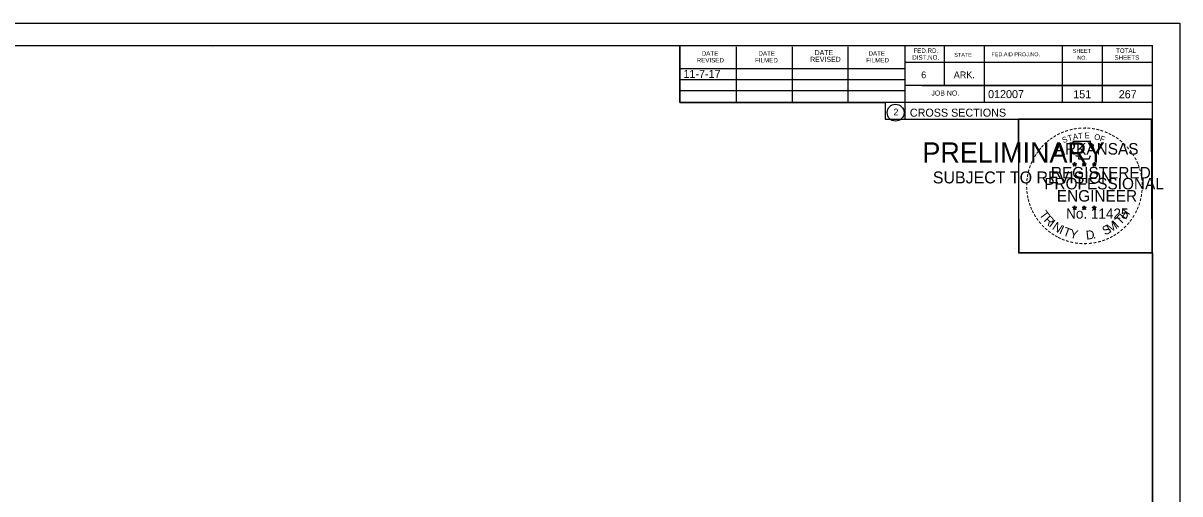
# Model space of a CAD drawing. Extents: x 1374311 to 1383814, y 384102 to 406278.
# Drawn here: x 1381590.3 to 1381791.6, y 384882.8 to 384964.6 of the extents above; entities that cross this region are included whole.
import ezdxf

# ---------------------------------------------------------------- set-up
doc = ezdxf.new("R2010")
doc.units = 0
for name, color, linetype in [('R_Border', 7, 'Continuous'), ('R_Border PE', 7, 'Continuous'), ('R_Border Prem', 7, 'Continuous'), ('R_Fin Surface', 7, 'Continuous'), ('R_No Plot', 7, 'Continuous'), ('R_Water', 7, 'Continuous')]:
    doc.layers.add(name, color=color, linetype=linetype)

msp = doc.modelspace()

# ---------------------------------------------------------------- linework, layer by layer
at = {"layer": 'R_Border'}
for p, q in [((1381470.66, 384960.72), (1381786.84, 384960.72)), ((1381623.18, 384960.46), (1381623.18, 384960.46)), ((1381623.18, 384960.46), (1381623.18, 384960.46)), ((1381704.58, 384950.84), (1381704.58, 384960.72)), ((1381714.44, 384950.84), (1381714.44, 384960.52)), ((1381724.2, 384950.84), (1381724.2, 384960.52)), ((1381733.88, 384950.84), (1381733.88, 384960.52)), ((1381743.74, 384960.72), (1381743.74, 384947.92)), ((1381750.58, 384960.72), (1381750.58, 384953.78)), ((1381757.52, 384960.72), (1381757.52, 384950.84)), ((1381771.1, 384960.72), (1381771.1, 384950.84)), ((1381778.04, 384960.72), (1381778.04, 384950.84)), ((1381786.84, 384755.26), (1381786.84, 384960.72)), ((1381786.84, 384957.78), (1381743.74, 384957.78)), ((1381786.84, 384957.8), (1381786.84, 384957.8)), ((1381704.58, 384956.7), (1381743.74, 384956.7)), ((1381704.58, 384954.84), (1381743.74, 384954.84)), ((1381704.58, 384950.84), (1381704.58, 384952.9)), ((1381704.58, 384952.9), (1381743.74, 384952.9)), ((1381786.84, 384953.78), (1381743.74, 384953.78)), ((1381746.7, 384953.78), (1381786.84, 384953.78)), ((1381786.84, 384950.84), (1381704.58, 384950.84)), ((1381743.74, 384947.92), (1381786.84, 384947.92))]:
    msp.add_line(p, q, dxfattribs=at)
msp.add_circle((1381742.12, 384949.05), 1.47, dxfattribs=at)
at = {"layer": 'R_Border PE'}
for p, q in [((1381772.92, 384940.17), (1381773.27, 384940.06)), ((1381772.92, 384940.17), (1381773.18, 384940.13)), ((1381772.92, 384940.17), (1381773.16, 384940.05)), ((1381773.06, 384939.77), (1381773.27, 384940.06)), ((1381773.06, 384939.77), (1381773.18, 384940.01)), ((1381773.06, 384939.77), (1381773.27, 384939.98)), ((1381773.27, 384940.43), (1381773.23, 384940.18)), ((1381773.27, 384940.06), (1381773.27, 384940.43)), ((1381773.27, 384940.43), (1381773.32, 384940.18)), ((1381773.62, 384940.17), (1381773.27, 384940.06)), ((1381773.48, 384939.77), (1381773.27, 384940.06)), ((1381773.48, 384939.77), (1381773.27, 384939.98)), ((1381773.62, 384940.17), (1381773.33, 384940.12)), ((1381773.48, 384939.77), (1381773.35, 384940.06)), ((1381773.62, 384940.17), (1381773.41, 384940.07)), ((1381774.59, 384940.17), (1381774.94, 384940.06)), ((1381774.59, 384940.17), (1381774.85, 384940.13)), ((1381774.59, 384940.17), (1381774.83, 384940.05)), ((1381774.73, 384939.77), (1381774.94, 384940.06)), ((1381774.73, 384939.77), (1381774.85, 384940.01)), ((1381774.73, 384939.77), (1381774.94, 384939.98)), ((1381774.94, 384940.43), (1381774.9, 384940.18)), ((1381774.94, 384940.06), (1381774.94, 384940.43)), ((1381774.94, 384940.43), (1381774.99, 384940.18)), ((1381775.29, 384940.17), (1381774.94, 384940.06)), ((1381775.15, 384939.77), (1381774.94, 384940.06)), ((1381775.15, 384939.77), (1381774.94, 384939.98)), ((1381775.29, 384940.17), (1381775, 384940.12)), ((1381775.15, 384939.77), (1381775.02, 384940.06)), ((1381775.29, 384940.17), (1381775.08, 384940.07)), ((1381776.36, 384940.16), (1381776.71, 384940.05)), ((1381776.36, 384940.16), (1381776.61, 384940.12)), ((1381776.36, 384940.16), (1381776.59, 384940.04)), ((1381776.49, 384939.75), (1381776.71, 384940.05)), ((1381776.49, 384939.75), (1381776.62, 384940)), ((1381776.49, 384939.75), (1381776.7, 384939.97)), ((1381776.71, 384940.42), (1381776.66, 384940.16)), ((1381776.92, 384939.75), (1381776.7, 384939.97)), ((1381776.71, 384940.05), (1381776.71, 384940.42)), ((1381776.71, 384940.42), (1381776.75, 384940.17)), ((1381777.05, 384940.16), (1381776.71, 384940.05)), ((1381776.92, 384939.75), (1381776.71, 384940.05)), ((1381777.05, 384940.16), (1381776.77, 384940.11)), ((1381776.92, 384939.75), (1381776.78, 384940.04)), ((1381777.05, 384940.16), (1381776.85, 384940.06)), ((1381773.27, 384932.85), (1381773.23, 384932.6)), ((1381773.27, 384932.49), (1381773.27, 384932.85)), ((1381773.27, 384932.85), (1381773.32, 384932.6)), ((1381774.94, 384932.85), (1381774.9, 384932.6)), ((1381774.94, 384932.49), (1381774.94, 384932.85)), ((1381774.94, 384932.85), (1381774.99, 384932.6)), ((1381776.7, 384932.84), (1381776.66, 384932.59)), ((1381776.7, 384932.48), (1381776.7, 384932.84)), ((1381776.7, 384932.84), (1381776.75, 384932.59)), ((1381772.92, 384932.6), (1381773.27, 384932.49)), ((1381772.92, 384932.6), (1381773.17, 384932.56)), ((1381772.92, 384932.6), (1381773.16, 384932.48)), ((1381773.05, 384932.19), (1381773.27, 384932.49)), ((1381773.05, 384932.19), (1381773.18, 384932.44)), ((1381773.05, 384932.19), (1381773.27, 384932.41)), ((1381773.61, 384932.6), (1381773.27, 384932.49)), ((1381773.48, 384932.19), (1381773.27, 384932.49)), ((1381773.48, 384932.19), (1381773.27, 384932.41)), ((1381773.61, 384932.6), (1381773.33, 384932.55)), ((1381773.48, 384932.19), (1381773.34, 384932.48)), ((1381773.61, 384932.6), (1381773.41, 384932.5)), ((1381774.59, 384932.6), (1381774.94, 384932.49)), ((1381774.59, 384932.6), (1381774.84, 384932.56)), ((1381774.59, 384932.6), (1381774.82, 384932.48)), ((1381774.72, 384932.19), (1381774.94, 384932.49)), ((1381774.72, 384932.19), (1381774.85, 384932.44)), ((1381774.72, 384932.19), (1381774.93, 384932.41)), ((1381775.15, 384932.19), (1381774.93, 384932.41)), ((1381775.28, 384932.6), (1381774.94, 384932.49)), ((1381775.15, 384932.19), (1381774.94, 384932.49)), ((1381775.28, 384932.6), (1381775, 384932.55)), ((1381775.15, 384932.19), (1381775.01, 384932.48)), ((1381775.28, 384932.6), (1381775.08, 384932.5)), ((1381776.35, 384932.59), (1381776.7, 384932.48)), ((1381776.35, 384932.59), (1381776.61, 384932.55)), ((1381776.35, 384932.59), (1381776.59, 384932.47)), ((1381776.49, 384932.18), (1381776.7, 384932.48)), ((1381776.49, 384932.18), (1381776.61, 384932.43)), ((1381776.49, 384932.18), (1381776.7, 384932.4)), ((1381777.05, 384932.59), (1381776.7, 384932.48)), ((1381776.92, 384932.18), (1381776.7, 384932.48)), ((1381776.92, 384932.18), (1381776.7, 384932.4)), ((1381777.05, 384932.59), (1381776.76, 384932.54)), ((1381776.92, 384932.18), (1381776.78, 384932.47)), ((1381777.05, 384932.59), (1381776.85, 384932.49))]:
    msp.add_line(p, q, dxfattribs=at)
for points in [[(1381772.96, 384944.05), (1381773.23, 384943.22)], [(1381776.47, 384943.13), (1381776.62, 384943.41), (1381775.93, 384943.39), (1381776.08, 384944.05), (1381772.96, 384944.05)], [(1381773.46, 384941.63), (1381773.46, 384941.54), (1381774.02, 384941.52), (1381773.96, 384941.05), (1381775.83, 384941.05), (1381776.04, 384941.59)], [(1381773.27, 384940.43), (1381773.48, 384939.77), (1381772.92, 384940.17), (1381773.62, 384940.17), (1381773.06, 384939.77), (1381773.27, 384940.43)], [(1381774.94, 384940.43), (1381775.15, 384939.77), (1381774.59, 384940.17), (1381775.29, 384940.17), (1381774.73, 384939.77), (1381774.94, 384940.43)], [(1381776.71, 384940.42), (1381776.92, 384939.75), (1381776.36, 384940.16), (1381777.05, 384940.16), (1381776.49, 384939.75), (1381776.71, 384940.42)], [(1381773.27, 384932.85), (1381773.48, 384932.19), (1381772.92, 384932.6), (1381773.61, 384932.6), (1381773.05, 384932.19), (1381773.27, 384932.85)], [(1381774.94, 384932.85), (1381775.15, 384932.19), (1381774.59, 384932.6), (1381775.28, 384932.6), (1381774.72, 384932.19), (1381774.94, 384932.85)], [(1381776.7, 384932.84), (1381776.92, 384932.18), (1381776.35, 384932.59), (1381777.05, 384932.59), (1381776.49, 384932.18), (1381776.7, 384932.84)]]:
    msp.add_lwpolyline(points, dxfattribs=at)
for centre, radius in [((1381773.27, 384940.06), 0.172), ((1381773.27, 384940.06), 0.145), ((1381773.27, 384940.06), 0.116), ((1381773.27, 384940.06), 0.0991), ((1381773.27, 384940.06), 0.0747), ((1381773.27, 384940.06), 0.0495), ((1381773.27, 384940.06), 0.0296), ((1381774.94, 384940.06), 0.172), ((1381774.94, 384940.06), 0.145), ((1381774.94, 384940.06), 0.116), ((1381774.94, 384940.06), 0.0991), ((1381774.94, 384940.06), 0.0747), ((1381774.94, 384940.06), 0.0495), ((1381774.94, 384940.06), 0.0296), ((1381776.7, 384940.05), 0.172), ((1381776.7, 384940.05), 0.145), ((1381776.7, 384940.05), 0.116), ((1381776.7, 384940.05), 0.0991), ((1381776.7, 384940.05), 0.0747), ((1381776.7, 384940.05), 0.0495), ((1381776.7, 384940.05), 0.0296), ((1381773.27, 384932.49), 0.172), ((1381773.27, 384932.49), 0.145), ((1381773.27, 384932.49), 0.116), ((1381773.27, 384932.49), 0.0991), ((1381773.27, 384932.49), 0.0747), ((1381773.27, 384932.49), 0.0495), ((1381773.27, 384932.49), 0.0296), ((1381774.94, 384932.49), 0.172), ((1381774.94, 384932.49), 0.145), ((1381774.94, 384932.49), 0.116), ((1381774.94, 384932.49), 0.0991), ((1381774.94, 384932.49), 0.0747), ((1381774.94, 384932.49), 0.0495), ((1381774.94, 384932.49), 0.0296), ((1381776.7, 384932.48), 0.172), ((1381776.7, 384932.48), 0.145), ((1381776.7, 384932.48), 0.116), ((1381776.7, 384932.48), 0.0991), ((1381776.7, 384932.48), 0.0747), ((1381776.7, 384932.48), 0.0495), ((1381776.7, 384932.48), 0.0296)]:
    msp.add_circle(centre, radius, dxfattribs=at)
at = {"layer": 'R_No Plot'}
for p, q in [((1381458.26, 384964.61), (1381791.59, 384964.61)), ((1381762.87, 384925.46), (1381762.87, 384925.46))]:
    msp.add_line(p, q, dxfattribs=at)
for points in [[(1381458.25, 384964.61), (1381791.59, 384964.61), (1381791.59, 384751.28), (1381458.25, 384751.28)], [(1381704.58, 384960.72), (1381704.58, 384950.84), (1381740.31, 384950.84), (1381740.31, 384947.92), (1381763.51, 384947.92), (1381763.51, 384924.7), (1381786.84, 384924.7), (1381786.84, 384755.26), (1381470.66, 384755.26), (1381470.66, 384960.72)], [(1381763.51, 384947.95), (1381786.61, 384947.95), (1381786.72, 384924.7), (1381763.62, 384924.7)]]:
    msp.add_lwpolyline(points, close=True, dxfattribs=at)

# ---------------------------------------------------------------- texts
at = {"layer": 'R_Border'}
for s, height, p in [('DATE', 0.782, (1381708.38, 384958.96)), ('DATE', 0.782, (1381718.24, 384958.96)), ('DATE', 0.879, (1381728.02, 384959.06)), ('DATE', 0.782, (1381737.4, 384958.96)), ('DIST.NO.', 0.782, (1381745.02, 384958.26)), ('FED.RD.', 0.782, (1381745.22, 384959.44)), ('STATE', 0.684, (1381752.34, 384958.76)), ('FED.AID PROJ.NO.', 0.684, (1381758.8, 384958.86)), ('SHEET', 0.684, (1381772.96, 384959.44)), ('NO.', 0.684, (1381773.74, 384958.26)), ('SHEETS', 0.782, (1381780.2, 384958.26)), ('TOTAL', 0.782, (1381780.48, 384959.44)), ('REVISED', 0.782, (1381707.5, 384957.78)), ('FILMED', 0.782, (1381717.66, 384957.78)), ('REVISED', 0.879, (1381727.24, 384957.88)), ('FILMED', 0.782, (1381737, 384957.78)), ('6', 1.17, (1381746.58, 384955.04)), ('ARK.', 1.172, (1381752.24, 384955.04)), ('JOB NO.', 0.879, (1381748.34, 384952.02)), ('012007', 1.4, (1381758.21, 384951.58)), ('2', 1.17, (1381741.74, 384948.57)), ('CROSS SECTIONS', 1.4, (1381744.6, 384948.35))]:
    msp.add_text(s, height=height, rotation=360, dxfattribs=at).set_placement(p)
at = {"layer": 'R_Border PE'}
for s, height, rotation, p in [('-', 1.6, 34.0636, (1381769.85, 384944.22)), ('-', 1.6, 28.7918, (1381770.44, 384944.59)), ('-', 1.6, 24.3072, (1381771.08, 384944.91)), ('S', 1, 21.594, (1381771.32, 384943.73)), ('-', 1.6, 19.1761, (1381771.71, 384945.18)), ('T', 1, 16.4036, (1381772.23, 384944.06)), ('-', 1.6, 13.6301, (1381772.46, 384945.42)), ('A', 1, 11.2132, (1381773.06, 384944.31)), ('-', 1.6, 10.2193, (1381773.14, 384945.58)), ('T', 1, 6.0228, (1381773.91, 384944.48)), ('-', 1.6, 5.8968, (1381773.87, 384945.69)), ('-', 1.6, 0.1862, (1381774.64, 384945.76)), ('E', 1, 0.8323, (1381775.01, 384944.59)), ('-', 1.6, 357.743, (1381775.36, 384945.75)), ('-', 1.6, 352.1617, (1381776.11, 384945.69)), ('O', 1, 350.4515, (1381776.62, 384944.38)), ('-', 1.6, 347.2049, (1381776.83, 384945.58)), ('F', 1, 340.0707, (1381777.57, 384944.15)), ('-', 1.6, 342.3362, (1381777.46, 384945.43)), ('-', 1.6, 337.8551, (1381778.2, 384945.2)), ('-', 1.6, 334.1211, (1381778.83, 384944.93)), ('-', 1.6, 329.6409, (1381779.41, 384944.65)), ('-', 1.6, 50.6142, (1381767.51, 384942.07)), ('-', 1.6, 48.423, (1381767.91, 384942.55)), ('-', 1.6, 42.9622, (1381768.36, 384943.03)), ('-', 1.6, 38.9507, (1381768.79, 384943.45)), ('-', 1.6, 36.2317, (1381769.27, 384943.83)), ('ARKANSAS', 2, 360, (1381769.82, 384941.76)), ('-', 1.6, 325.8627, (1381780.05, 384944.29)), ('-', 1.6, 320.5297, (1381780.66, 384943.86)), ('-', 1.6, 315.5786, (1381781.26, 384943.37)), ('-', 1.6, 309.8797, (1381781.83, 384942.82)), ('-', 1.6, 62.8713, (1381766.46, 384940.36)), ('-', 1.6, 58.0706, (1381766.77, 384940.97)), ('-', 1.6, 54.2325, (1381767.1, 384941.5)), ('-', 1.6, 306.6522, (1381782.35, 384942.22)), ('-', 1.4, 303.6753, (1381782.84, 384941.65)), ('-', 1.6, 299.6684, (1381783.16, 384941.05)), ('-', 1.6, 75.461, (1381765.78, 384938.41)), ('-', 1.6, 72.3945, (1381765.98, 384939.12)), ('-', 1.6, 67.7743, (1381766.2, 384939.75)), ('REGISTERED', 2, 360, (1381769.14, 384937.61)), ('DWB', 0.01, 360, (1381773.26, 384940.06)), ('DWB', 0.01, 360, (1381774.93, 384940.06)), ('DWB', 0.01, 360, (1381776.69, 384940.05)), ('-', 1.6, 294.6628, (1381783.48, 384940.43)), ('-', 1.6, 290.5728, (1381783.74, 384939.86)), ('-', 1.6, 285.1233, (1381783.97, 384939.28)), ('-', 1.6, 89.0622, (1381765.55, 384936.3)), ('-', 1.6, 85.1863, (1381765.57, 384937)), ('-', 1.6, 81.2013, (1381765.65, 384937.69)), ('PROFESSIONAL', 2, 360, (1381767.99, 384935.71)), ('-', 1.6, 280.5493, (1381784.17, 384938.54)), ('-', 1.6, 276.5962, (1381784.33, 384937.77)), ('-', 1.6, 274.3301, (1381784.39, 384937.05)), ('-', 1.6, 94.1959, (1381765.58, 384935.58)), ('-', 1.6, 98.9479, (1381765.66, 384934.91)), ('ENGINEER', 2, 360, (1381770.18, 384933.59)), ('-', 1.6, 260.9953, (1381784.34, 384935.09)), ('-', 1.6, 263.5172, (1381784.41, 384935.75)), ('-', 1.6, 269.9407, (1381784.43, 384936.41)), ('-', 1.6, 101.7149, (1381765.79, 384934.18)), ('-', 1.6, 105.4578, (1381765.95, 384933.58)), ('-', 1.6, 109.0874, (1381766.17, 384932.95)), ('-', 1.6, 252.8681, (1381784.05, 384933.7)), ('-', 1.6, 255.7626, (1381784.23, 384934.42)), ('-', 1.6, 114.0643, (1381766.42, 384932.35)), ('-', 1.6, 115.7289, (1381766.73, 384931.74)), ('-', 1.6, 120.4471, (1381767.08, 384931.15)), ('-', 1.6, 125.8934, (1381767.49, 384930.59)), ('T', 1.54, 306.0406, (1381767.03, 384931.33)), ('R', 1.54, 314.005, (1381767.79, 384930.28)), ('No. 11425', 1.757, 360, (1381771.8, 384930.63)), ('DWB', 0.01, 360, (1381773.25, 384932.48)), ('DWB', 0.01, 360, (1381774.92, 384932.48)), ('DWB', 0.01, 360, (1381776.69, 384932.47)), ('T', 1.54, 46.6444, (1381781.26, 384929.42)), ('H', 1.54, 54.6088, (1381782.15, 384930.36)), ('-', 1.6, 239.0712, (1381783.17, 384931.64)), ('-', 1.6, 244.6197, (1381783.56, 384932.39)), ('-', 1.6, 247.8887, (1381783.82, 384933.02)), ('-', 1.6, 130.7181, (1381767.95, 384930.04)), ('-', 1.6, 134.2238, (1381768.47, 384929.49)), ('-', 1.6, 138.9338, (1381768.99, 384929.03)), ('I', 1.54, 321.9694, (1381768.69, 384929.35)), ('N', 1.54, 326.5002, (1381769.26, 384928.88)), ('I', 1.54, 335.3603, (1381770.47, 384928.09)), ('T', 1.54, 339.8912, (1381771.13, 384927.76)), ('Y', 1.54, 347.8556, (1381772.34, 384927.32)), ('S', 1.54, 26.9312, (1381778.57, 384927.69)), ('M', 1.54, 32.6563, (1381779.41, 384928.1)), ('I', 1.54, 42.1136, (1381780.7, 384928.94)), ('-', 1.6, 221.0851, (1381781.33, 384929.35)), ('-', 1.6, 225.7653, (1381781.86, 384929.86)), ('-', 1.6, 231.2538, (1381782.34, 384930.42)), ('-', 1.6, 233.8452, (1381782.77, 384930.99)), ('-', 1.6, 144.6463, (1381769.55, 384928.62)), ('-', 1.6, 148.0898, (1381770.11, 384928.25)), ('-', 1.6, 151.5704, (1381770.69, 384927.93)), ('-', 1.6, 154.6002, (1381771.21, 384927.68)), ('-', 1.6, 158.5612, (1381771.83, 384927.42)), ('-', 1.6, 162.7983, (1381772.52, 384927.21)), ('D', 1.54, 6.3969, (1381775.33, 384926.96)), ('.', 1.54, 13.7642, (1381776.52, 384927.09)), ('-', 1.6, 195.4743, (1381777.77, 384927.31)), ('-', 1.6, 200.7184, (1381778.45, 384927.55)), ('-', 1.6, 204.2516, (1381779.07, 384927.83)), ('-', 1.6, 207.3568, (1381779.69, 384928.14)), ('-', 1.6, 212.2491, (1381780.25, 384928.49)), ('-', 1.6, 215.7363, (1381780.79, 384928.88)), ('-', 1.6, 167.5555, (1381773.24, 384927.05)), ('-', 1.6, 173.1155, (1381774.01, 384926.94)), ('-', 1.6, 176.5183, (1381774.76, 384926.88)), ('-', 1.6, 181.5918, (1381775.5, 384926.9)), ('-', 1.6, 185.8167, (1381776.31, 384926.98)), ('-', 1.6, 191.2858, (1381777.04, 384927.11))]:
    msp.add_text(s, height=height, rotation=rotation, dxfattribs=at).set_placement(p)
at = {"layer": 'R_Border Prem'}
for s, height, p in [('PRELIMINARY', 3.5, (1381746.79, 384940.38)), ('DWB', 0.01, (1381747.53, 384942.23)), ('SUBJECT TO REVISION', 2.0751, (1381748.6, 384936.75))]:
    msp.add_text(s, height=height, rotation=360, dxfattribs=at).set_placement(p)
at = {"layer": 'R_Fin Surface'}
msp.add_text('11-7-17', height=1.4, dxfattribs=at).set_placement((1381705.2, 384955.08))
at = {"layer": 'R_Water'}
for s, p in [('151', (1381773.03, 384951.55)), ('267', (1381780.95, 384951.55))]:
    msp.add_text(s, height=1.4, rotation=360, dxfattribs=at).set_placement(p)

doc.saveas('drawing.dxf')
